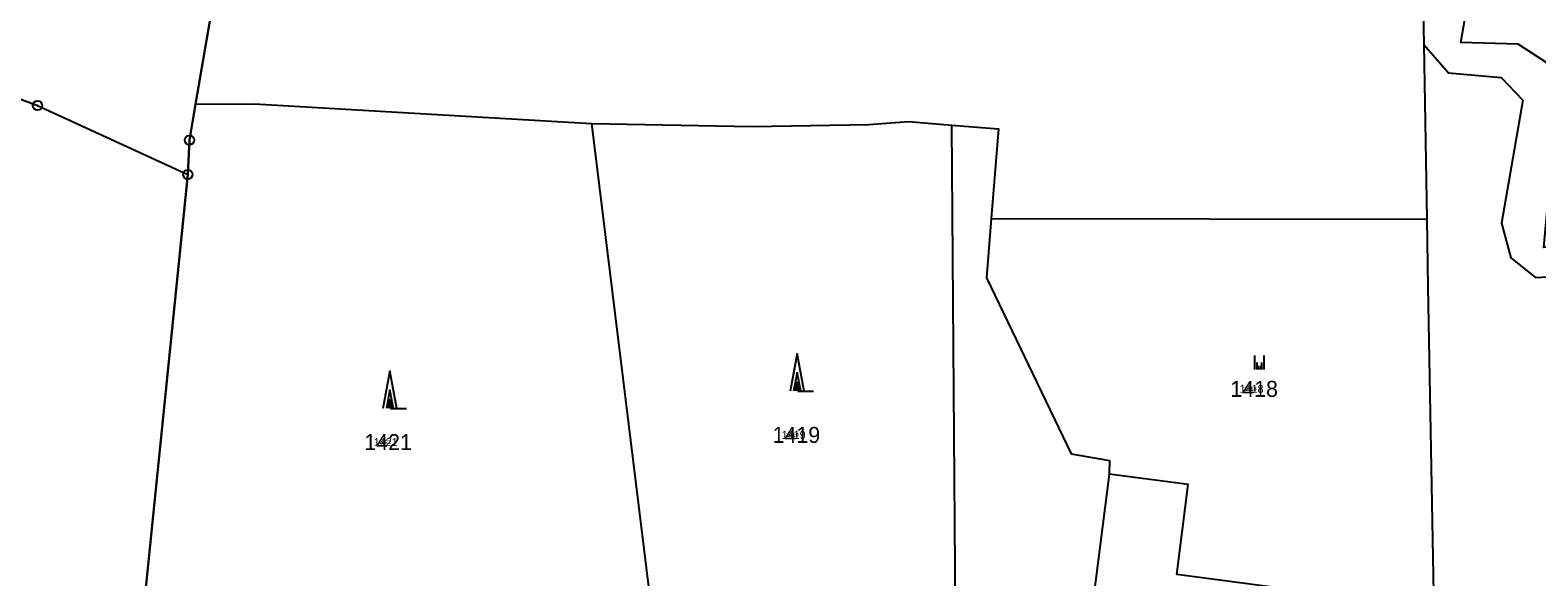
# Model space of a CAD drawing. Extents: x -744652 to -739090, y -980828 to -975855.
# Drawn here: x -741846.2 to -741686.2, y -978788.5 to -978730.5 of the extents above; entities that cross this region are included whole.
import ezdxf

# ---------------------------------------------------------------- set-up
doc = ezdxf.new("R2010")
doc.units = 0
for name, color, linetype in [('KAT_01_hranice KU', 7, 'Continuous'), ('KAT_02_hranice parcel', 7, 'Continuous'), ('KAT_03_1000_čísla parcelní', 7, 'Continuous'), ('KAT_03_100_čísla parcelní', 7, 'Continuous'), ('KAT_03_250_čísla parcelní', 7, 'Continuous'), ('KAT_03_500_čísla parcelní', 7, 'Continuous'), ('KAT_05_1000_značky kultur', 7, 'Continuous'), ('KAT_05_100_značky kultur', 7, 'Continuous'), ('KAT_05_250_značky kultur', 7, 'Continuous'), ('KAT_05_500_značky kultur', 7, 'Continuous'), ('KAT_11_značky bodu BP', 7, 'Continuous')]:
    doc.layers.add(name, color=color, linetype=linetype)

msp = doc.modelspace()

# ---------------------------------------------------------------- linework, layer by layer
at = {"layer": 'KAT_01_hranice KU'}
msp.add_lwpolyline([(-741798.65, -978597.08), (-741808.54, -978644.45), (-741817.44, -978673.77), (-741828.59, -978738.33), (-741829.25, -978742.15), (-741829.42, -978745.8), (-741834.68, -978797.61), (-741835.56, -978818.63), (-741834.39, -978818.59), (-741833.13, -978829.98), (-741831.56, -978837.44), (-741800.71, -978841.57), (-741798.32, -978841.89), (-741797.81, -978844.85), (-741797.75, -978845.17), (-741797.19, -978848.44), (-741793.33, -978870.82), (-741772.86, -978867.41), (-741736.53, -978877.84), (-741709.02, -978891.15), (-741724.37, -978911.25)], dxfattribs=at)
at = {"layer": 'KAT_02_hranice parcel'}
for p, q in [((-741828.59, -978738.33), (-741817.44, -978673.77)), ((-741828.59, -978738.33), (-741817.44, -978673.77)), ((-741698.44, -978719.23), (-741698.17, -978732)), ((-741698.17, -978732), (-741697.87, -978750.54)), ((-741829.25, -978742.15), (-741828.59, -978738.33)), ((-741829.25, -978742.15), (-741828.59, -978738.33)), ((-741786.56, -978740.39), (-741779.66, -978796.25)), ((-741747.63, -978824.34), (-741748.3, -978740.56)), ((-741829.42, -978745.8), (-741829.25, -978742.15)), ((-741829.42, -978745.8), (-741829.25, -978742.15)), ((-741834.68, -978797.61), (-741829.42, -978745.8)), ((-741834.68, -978797.61), (-741829.42, -978745.8)), ((-741744.11, -978750.48), (-741697.87, -978750.54))]:
    msp.add_line(p, q, dxfattribs=at)
for points in [[(-741905.86, -978715.79), (-741899.96, -978717.79), (-741895.09, -978719.38), (-741884.26, -978722.89), (-741863.2, -978730.47), (-741853.37, -978735.46), (-741845.37, -978738.49), (-741829.42, -978745.8)], [(-741605.68, -978852.79), (-741609.25, -978837.97), (-741615.68, -978821.74), (-741621.42, -978816.14), (-741626.7, -978806.97), (-741630.21, -978803.87), (-741633.22, -978796.04), (-741655.17, -978776.13), (-741666.31, -978764.66), (-741675.69, -978755.25), (-741679.99, -978753.29), (-741685.44, -978753.55), (-741684.62, -978744.62), (-741683.59, -978734.96), (-741688.14, -978731.99), (-741694.23, -978731.8), (-741693.48, -978727.27), (-741694.57, -978721.15), (-741698.44, -978719.23)], [(-741698.17, -978732), (-741695.54, -978735.03), (-741689.96, -978735.51), (-741687.67, -978737.91), (-741689.92, -978750.97), (-741688.92, -978754.63), (-741686.3, -978756.72), (-741681.02, -978756.46), (-741671.16, -978769.23), (-741656.74, -978780.59), (-741651.53, -978784.76), (-741646.33, -978788.68), (-741641.4, -978793.96), (-741632.85, -978806.86), (-741629.62, -978809.71), (-741627.81, -978811.92), (-741625.25, -978817.3), (-741618.98, -978822.9), (-741611.14, -978838.4), (-741607.64, -978852.98)], [(-741828.59, -978738.33), (-741822.35, -978738.3), (-741786.56, -978740.39)], [(-741786.56, -978740.39), (-741769.48, -978740.7), (-741757.09, -978740.49), (-741752.89, -978740.19), (-741748.3, -978740.56)], [(-741748.3, -978740.56), (-741743.35, -978740.95), (-741744.11, -978750.48)], [(-741744.11, -978750.48), (-741744.61, -978756.75), (-741735.61, -978775.44), (-741731.54, -978776.14), (-741731.59, -978777.58)], [(-741697.87, -978750.54), (-741697.75, -978757.73), (-741697.15, -978790.26)], [(-741731.59, -978777.58), (-741734.12, -978797.56), (-741734.77, -978802.6), (-741737.75, -978825.61)], [(-741703.27, -978791.01), (-741708.62, -978790.3), (-741724.39, -978788.23), (-741723.18, -978778.7), (-741731.59, -978777.58)]]:
    msp.add_lwpolyline(points, dxfattribs=at)
at = {"layer": 'KAT_05_1000_značky kultur'}
for p, q in [((-741764.72, -978764.79), (-741765.47, -978768.79)), ((-741763.97, -978768.79), (-741764.72, -978764.79)), ((-741716.13, -978766.49), (-741716.13, -978764.99)), ((-741715.13, -978766.49), (-741715.13, -978764.99)), ((-741807.96, -978766.63), (-741808.71, -978770.63)), ((-741807.21, -978770.63), (-741807.96, -978766.63)), ((-741763.97, -978768.79), (-741762.97, -978768.79)), ((-741807.21, -978770.63), (-741806.21, -978770.63))]:
    msp.add_line(p, q, dxfattribs=at)
at = {"layer": 'KAT_05_100_značky kultur'}
for p, q in [((-741715.67, -978766.49), (-741715.67, -978766.34)), ((-741715.57, -978766.49), (-741715.57, -978766.34)), ((-741764.72, -978768.39), (-741764.8, -978768.79)), ((-741764.65, -978768.79), (-741764.72, -978768.39)), ((-741807.96, -978770.23), (-741808.04, -978770.63)), ((-741807.89, -978770.63), (-741807.96, -978770.23)), ((-741764.65, -978768.79), (-741764.55, -978768.79)), ((-741807.89, -978770.63), (-741807.79, -978770.63))]:
    msp.add_line(p, q, dxfattribs=at)
at = {"layer": 'KAT_05_250_značky kultur'}
for p, q in [((-741715.75, -978766.49), (-741715.75, -978766.11)), ((-741715.5, -978766.49), (-741715.5, -978766.11)), ((-741764.72, -978767.79), (-741764.91, -978768.79)), ((-741764.53, -978768.79), (-741764.72, -978767.79)), ((-741807.96, -978769.63), (-741808.15, -978770.63)), ((-741807.77, -978770.63), (-741807.96, -978769.63)), ((-741764.53, -978768.79), (-741764.28, -978768.79)), ((-741807.77, -978770.63), (-741807.52, -978770.63))]:
    msp.add_line(p, q, dxfattribs=at)
at = {"layer": 'KAT_05_500_značky kultur'}
for p, q in [((-741764.72, -978766.79), (-741765.09, -978768.79)), ((-741764.34, -978768.79), (-741764.72, -978766.79)), ((-741715.88, -978766.49), (-741715.88, -978765.74)), ((-741715.38, -978766.49), (-741715.38, -978765.74)), ((-741807.96, -978768.63), (-741808.33, -978770.63)), ((-741807.58, -978770.63), (-741807.96, -978768.63)), ((-741764.34, -978768.79), (-741763.85, -978768.79)), ((-741807.58, -978770.63), (-741807.09, -978770.63))]:
    msp.add_line(p, q, dxfattribs=at)
at = {"layer": 'KAT_11_značky bodu BP'}
for centre, radius in [((-741845.37, -978738.49), 0.5), ((-741845.37, -978738.49), 0.0303), ((-741829.25, -978742.15), 0.5), ((-741829.25, -978742.15), 0.0303), ((-741829.42, -978745.8), 0.5), ((-741829.42, -978745.8), 0.0303)]:
    msp.add_circle(centre, radius, dxfattribs=at)

# ---------------------------------------------------------------- texts
at = {"layer": 'KAT_03_1000_čísla parcelní'}
for s, p in [('1418', (-741718.72, -978769.39)), ('1421', (-741810.68, -978775.04)), ('1419', (-741767.33, -978774.27))]:
    msp.add_text(s, height=1.7, dxfattribs=at).set_placement(p)
at = {"layer": 'KAT_03_100_čísla parcelní'}
for s, p in [('1418', (-741716.95, -978768.62)), ('1419', (-741765.57, -978773.5)), ('1421', (-741808.86, -978774.27))]:
    msp.add_text(s, height=0.17, dxfattribs=at).set_placement(p)
at = {"layer": 'KAT_03_250_čísla parcelní'}
for s, p in [('1418', (-741717.24, -978768.75)), ('1419', (-741765.87, -978773.63)), ('1421', (-741809.16, -978774.4))]:
    msp.add_text(s, height=0.425, dxfattribs=at).set_placement(p)
at = {"layer": 'KAT_03_500_čísla parcelní'}
for s, p in [('1418', (-741717.73, -978768.96)), ('1419', (-741766.35, -978773.84)), ('1421', (-741809.67, -978774.61))]:
    msp.add_text(s, height=0.85, dxfattribs=at).set_placement(p)

doc.saveas('drawing.dxf')
